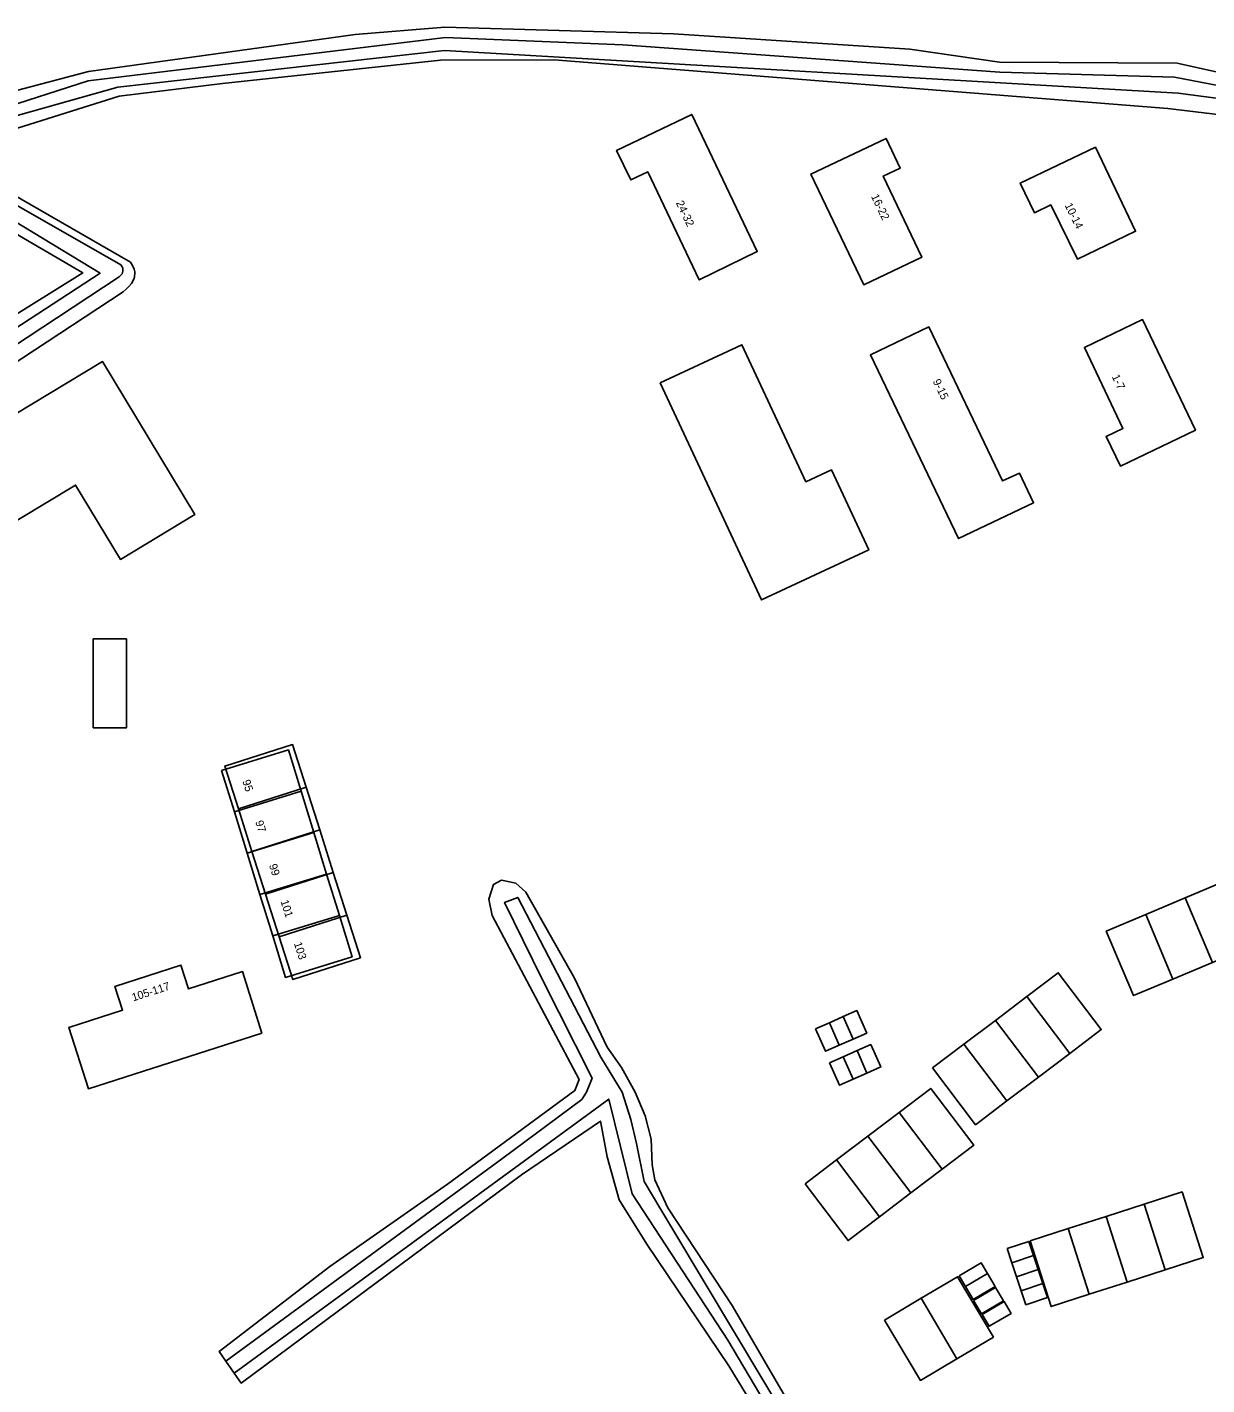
# Model space of a CAD drawing. Extents: x 159451 to 160664, y 388402 to 389723.
# Drawn here: x 159869.7 to 160017.1, y 389378.7 to 389548.3 of the extents above; entities that cross this region are included whole.
import ezdxf

# ---------------------------------------------------------------- set-up
doc = ezdxf.new("R2010")
doc.units = 0
for name, color, linetype in [('IMGEO_Groenvoorziening', 7, 'Continuous'), ('IMGEO_Oever', 7, 'Continuous'), ('IMGEO_Pand', 7, 'Continuous'), ('IMGEO_Pand_nummerreeks', 7, 'Continuous'), ('IMGEO_Pand_vergunning_verleend', 7, 'Continuous'), ('IMGEO_Waterloop', 7, 'Continuous')]:
    doc.layers.add(name, color=color, linetype=linetype)

msp = doc.modelspace()

# ---------------------------------------------------------------- linework, layer by layer
at = {"layer": 'IMGEO_Groenvoorziening'}
for points in [[(159864.26, 389539.27), (159877.37, 389542.72), (159910.67, 389547.35), (159921.89, 389548.25), (159950.46, 389547.42), (159979.98, 389545.51), (159991.18, 389543.87), (160013.37, 389543.74), (160026.85, 389540.77), (160059.3, 389537.37), (160076.74, 389535.9), (160093.1, 389532.4), (160106.88, 389532.52)], [(160094.37, 389528.6), (160093.68, 389522.77), (160090.33, 389523.17), (160090.94, 389528.33), (160076.45, 389531.72), (160041.63, 389534.55), (160012.22, 389538.08), (159935.54, 389544.19), (159921.34, 389544.14), (159894.12, 389541.21), (159881.2, 389539.62), (159858.79, 389532.6), (159882.61, 389518.89), (159882.88, 389518.48), (159883.08, 389518.04), (159883.14, 389517.69), (159883.16, 389517.57), (159883.13, 389517.08), (159883.07, 389516.85), (159882.73, 389516.23), (159882.42, 389515.86), (159882.06, 389515.52), (159881.7, 389515.21), (159821.76, 389475.8)], [(159815.03, 389479.17), (159876.64, 389517.57), (159858.8, 389527.98)], [(159966.8, 389365.6), (159957.37, 389381.03), (159947.14, 389396.23), (159943.66, 389401.77), (159942.19, 389407.16), (159941.35, 389411.59), (159931.47, 389404.89), (159896.45, 389378.88), (159895.58, 389380.11), (159894.54, 389381.6), (159893.69, 389382.82), (159907.5, 389393.46), (159922.23, 389403.72), (159938.12, 389415.41), (159938.68, 389416.82), (159927.82, 389437.27), (159927.38, 389439.33), (159927.97, 389441.16), (159928.96, 389441.71), (159930.75, 389441.34), (159931.99, 389440.21), (159938.08, 389429.46), (159942.16, 389420.84), (159943.96, 389418.29), (159945.66, 389415.23), (159946.9, 389412.25), (159947.66, 389409.36), (159947.78, 389406.13), (159948.12, 389404.27), (159949.76, 389400.78), (159957.78, 389388.59), (159970.06, 389367.46)]]:
    msp.add_lwpolyline(points, dxfattribs=at)
for points in [[(159960.91, 389520.23), (159953.67, 389516.68), (159947.23, 389530.16), (159945.12, 389529.17), (159943.35, 389532.86), (159952.74, 389537.35)], [(159974.22, 389516.08), (159967.63, 389529.9), (159977.01, 389534.35), (159978.78, 389530.65), (159976.67, 389529.64), (159981.49, 389519.54)], [(160000.92, 389519.29), (159997.61, 389526.05), (159995.55, 389525.07), (159993.78, 389528.77), (160003.18, 389533.26), (160008.18, 389522.76)], [(160006.29, 389493.42), (160004.51, 389497.13), (160006.61, 389498.14), (160001.8, 389508.25), (160009.07, 389511.73), (160015.67, 389497.9)], [(159986.07, 389484.37), (159975.08, 389507.33), (159982.35, 389510.81), (159991.56, 389491.57), (159993.67, 389492.55), (159995.44, 389488.85)], [(159906.25, 389447.98), (159907.95, 389442.65), (159909.65, 389437.33), (159911.35, 389432), (159902.88, 389429.3), (159901.19, 389434.63), (159899.49, 389439.96), (159897.79, 389445.29), (159896.1, 389450.61), (159894.39, 389455.96), (159902.86, 389458.64), (159904.55, 389453.31)], [(159899.04, 389422.61), (159877.36, 389415.64), (159874.9, 389423.3), (159881.62, 389425.47), (159880.66, 389428.43), (159888.91, 389431.09), (159889.86, 389428.12), (159896.59, 389430.28)]]:
    msp.add_lwpolyline(points, close=True, dxfattribs=at)
at = {"layer": 'IMGEO_Oever'}
for points in [[(159854.53, 389534.2), (159877.32, 389541.54), (159921.96, 389546.95), (159944.13, 389546.06), (159991.21, 389542.62), (160013.05, 389542.02), (160027.34, 389539.24), (160076.46, 389534.42), (160093.15, 389531.13), (160106.86, 389531.48)], [(160106.88, 389532.52), (160093.1, 389532.4), (160076.74, 389535.9), (160059.3, 389537.37), (160026.85, 389540.77), (160013.37, 389543.74), (159991.18, 389543.87), (159979.98, 389545.51), (159950.46, 389547.42), (159921.89, 389548.25), (159910.67, 389547.35), (159877.37, 389542.72), (159864.26, 389539.27)], [(160101.81, 389529.55), (160093.23, 389529.36), (160092.58, 389524.23), (160091.46, 389524.26), (160091.88, 389529.28), (160076.32, 389532.99), (160052.78, 389534.86), (160013.5, 389540), (159921.84, 389545.35), (159881.02, 389540.75), (159867.27, 389536.87)], [(159821.76, 389475.8), (159881.7, 389515.21), (159882.06, 389515.52), (159882.42, 389515.86), (159882.73, 389516.23), (159883.07, 389516.85), (159883.13, 389517.08), (159883.16, 389517.57), (159883.14, 389517.69), (159883.08, 389518.04), (159882.88, 389518.48), (159882.61, 389518.89), (159858.79, 389532.6), (159881.2, 389539.62), (159894.12, 389541.21), (159921.34, 389544.14), (159935.54, 389544.19), (160012.22, 389538.08), (160041.63, 389534.55), (160076.45, 389531.72), (160090.94, 389528.33), (160090.33, 389523.17), (160093.68, 389522.77), (160094.37, 389528.6)], [(159818.15, 389477.97), (159878.82, 389517.52), (159853.88, 389532.62)], [(159856.18, 389532.97), (159881.4, 389518.55), (159881.57, 389518.31), (159881.65, 389518.15), (159881.67, 389517.77), (159881.56, 389517.46), (159881.41, 389517.26), (159881.21, 389517.06), (159819.88, 389476.66)], [(159858.8, 389527.98), (159876.64, 389517.57), (159815.03, 389479.17)], [(159970.06, 389367.46), (159957.78, 389388.59), (159949.76, 389400.78), (159948.12, 389404.27), (159947.78, 389406.13), (159947.66, 389409.36), (159946.9, 389412.25), (159945.66, 389415.23), (159943.96, 389418.29), (159942.16, 389420.84), (159938.08, 389429.46), (159931.99, 389440.21), (159930.75, 389441.34), (159928.96, 389441.71), (159927.97, 389441.16), (159927.38, 389439.33), (159927.82, 389437.27), (159938.68, 389416.82), (159938.12, 389415.41), (159922.23, 389403.72), (159907.5, 389393.46), (159893.69, 389382.82), (159894.54, 389381.6), (159929.14, 389406.98), (159939.02, 389414.32), (159939.59, 389415.23), (159940.29, 389416.97), (159934.06, 389429.35), (159929.35, 389438.93), (159930.99, 389439.55), (159941.39, 389419.58), (159944.05, 389415.23), (159945.14, 389411.82), (159945.85, 389408.79), (159946.78, 389404.04), (159948.86, 389400.56), (159950.48, 389397.86), (159969.06, 389366.84)], [(159967.9, 389366.27), (159957.24, 389384.26), (159945.31, 389402.53), (159942.37, 389414.35), (159895.58, 389380.11), (159896.45, 389378.88), (159931.47, 389404.89), (159941.35, 389411.59), (159942.19, 389407.16), (159943.66, 389401.77), (159947.14, 389396.23), (159957.37, 389381.03), (159966.8, 389365.6)]]:
    msp.add_lwpolyline(points, dxfattribs=at)
at = {"layer": 'IMGEO_Pand'}
for points in [[(159952.74, 389537.35), (159943.35, 389532.86), (159945.12, 389529.17), (159947.23, 389530.16), (159953.67, 389516.68), (159960.91, 389520.23)], [(159976.67, 389529.64), (159978.78, 389530.65), (159977.01, 389534.35), (159967.63, 389529.9), (159974.22, 389516.08), (159981.49, 389519.54)], [(160003.18, 389533.26), (159993.78, 389528.77), (159995.55, 389525.07), (159997.61, 389526.05), (160000.92, 389519.29), (160008.18, 389522.76)], [(160009.07, 389511.73), (160001.8, 389508.25), (160006.61, 389498.14), (160004.51, 389497.13), (160006.29, 389493.42), (160015.67, 389497.9)], [(159982.35, 389510.81), (159975.08, 389507.33), (159986.07, 389484.37), (159995.44, 389488.85), (159993.67, 389492.55), (159991.56, 389491.57)], [(159902.86, 389458.64), (159894.39, 389455.96), (159896.1, 389450.61), (159904.55, 389453.31)], [(159904.55, 389453.31), (159896.1, 389450.61), (159897.79, 389445.29), (159906.25, 389447.98)], [(159906.25, 389447.98), (159897.79, 389445.29), (159899.49, 389439.96), (159907.95, 389442.65)], [(159907.95, 389442.65), (159899.49, 389439.96), (159901.19, 389434.63), (159909.65, 389437.33)], [(159909.65, 389437.33), (159901.19, 389434.63), (159902.88, 389429.3), (159911.35, 389432)], [(159899.04, 389422.61), (159896.59, 389430.28), (159889.86, 389428.12), (159888.91, 389431.09), (159880.66, 389428.43), (159881.62, 389425.47), (159874.9, 389423.3), (159877.36, 389415.64)]]:
    msp.add_lwpolyline(points, close=True, dxfattribs=at)
at = {"layer": 'IMGEO_Pand_vergunning_verleend'}
for points in [[(159948.81, 389503.83), (159959.01, 389508.58), (159966.98, 389491.47), (159970.19, 389492.97), (159974.85, 389482.95), (159961.44, 389476.7)], [(159859.2, 389494.48), (159879.13, 389506.48), (159890.64, 389487.37), (159881.35, 389481.77), (159875.76, 389491.06), (159865.11, 389484.66)], [(159877.97, 389460.72), (159877.97, 389471.84), (159882.1, 389471.84), (159882.1, 389460.72)], [(159894, 389455.4), (159902.34, 389457.97), (159903.94, 389452.8), (159895.6, 389450.23)], [(159895.6, 389450.23), (159903.94, 389452.8), (159905.53, 389447.64), (159897.19, 389445.07)], [(159897.19, 389445.07), (159905.53, 389447.64), (159907.12, 389442.47), (159898.78, 389439.9)], [(159898.78, 389439.9), (159907.12, 389442.47), (159908.72, 389437.3), (159900.38, 389434.73)], [(160014.38, 389439.49), (160018.94, 389441.42), (160022.34, 389433.35), (160017.78, 389431.43)], [(160009.46, 389437.41), (160014.38, 389439.49), (160017.78, 389431.43), (160012.86, 389429.35)], [(159900.38, 389434.73), (159908.72, 389437.3), (159910.31, 389432.14), (159901.97, 389429.56)], [(160004.53, 389435.34), (160009.46, 389437.41), (160012.86, 389429.35), (160007.93, 389427.28)], [(159994.6, 389427.16), (159998.52, 389430.13), (160003.89, 389423.04), (159999.97, 389420.07)], [(159990.67, 389424.19), (159994.6, 389427.16), (159999.97, 389420.07), (159996.04, 389417.09)], [(159969.93, 389423.9), (159971.65, 389424.66), (159972.89, 389421.85), (159971.17, 389421.09)], [(159971.65, 389424.66), (159973.38, 389425.42), (159974.61, 389422.61), (159972.89, 389421.85)], [(159968.21, 389423.14), (159969.93, 389423.9), (159971.17, 389421.09), (159969.45, 389420.33)], [(159986.75, 389421.21), (159990.67, 389424.19), (159996.04, 389417.09), (159992.12, 389414.12)], [(159973.39, 389420.41), (159975.11, 389421.17), (159976.35, 389418.37), (159974.63, 389417.61)], [(159982.82, 389418.24), (159986.75, 389421.21), (159992.12, 389414.12), (159988.19, 389411.15)], [(159969.94, 389418.89), (159971.67, 389419.65), (159972.91, 389416.85), (159971.18, 389416.08)], [(159971.67, 389419.65), (159973.39, 389420.41), (159974.63, 389417.61), (159972.91, 389416.85)], [(159978.66, 389412.7), (159982.59, 389415.68), (159987.96, 389408.58), (159984.04, 389405.61)], [(159974.74, 389409.73), (159978.66, 389412.7), (159984.04, 389405.61), (159980.11, 389402.64)], [(159970.81, 389406.75), (159974.74, 389409.73), (159980.11, 389402.64), (159976.18, 389399.66)], [(159966.89, 389403.78), (159970.81, 389406.75), (159976.18, 389399.66), (159972.26, 389396.69)], [(160009.25, 389401.23), (160014, 389402.76), (160016.64, 389394.56), (160011.9, 389393.03)], [(160004.51, 389399.7), (160009.25, 389401.23), (160011.9, 389393.03), (160007.15, 389391.5)], [(159999.77, 389398.17), (160004.51, 389399.7), (160007.15, 389391.5), (160002.41, 389389.97)], [(159995.02, 389396.64), (159999.77, 389398.17), (160002.41, 389389.97), (159997.66, 389388.44)], [(159992.14, 389395.68), (159994.86, 389396.58), (159995.44, 389394.83), (159992.72, 389393.92)], [(159992.72, 389393.92), (159995.44, 389394.83), (159996.02, 389393.08), (159993.31, 389392.17)], [(159986.14, 389392.29), (159988.89, 389393.91), (159989.68, 389392.57), (159986.93, 389390.95)], [(159986.93, 389390.95), (159989.68, 389392.57), (159990.64, 389390.96), (159987.89, 389389.34)], [(159993.31, 389392.17), (159996.02, 389393.08), (159996.61, 389391.33), (159993.89, 389390.42)], [(159981.39, 389389.47), (159985.95, 389392.17), (159990.43, 389384.63), (159985.86, 389381.92)], [(159987.95, 389389.2), (159990.7, 389390.82), (159991.67, 389389.17), (159988.92, 389387.55)], [(159993.89, 389390.42), (159996.61, 389391.33), (159997.19, 389389.57), (159994.48, 389388.67)], [(159976.83, 389386.76), (159981.39, 389389.47), (159985.86, 389381.92), (159981.3, 389379.22)], [(159989.02, 389387.44), (159991.77, 389389.06), (159992.64, 389387.59), (159989.89, 389385.97)]]:
    msp.add_lwpolyline(points, close=True, dxfattribs=at)
at = {"layer": 'IMGEO_Waterloop'}
for points in [[(160106.86, 389531.48), (160093.15, 389531.13), (160076.46, 389534.42), (160027.34, 389539.24), (160013.05, 389542.02), (159991.21, 389542.62), (159944.13, 389546.06), (159921.96, 389546.95), (159877.32, 389541.54), (159854.53, 389534.2)], [(159867.27, 389536.87), (159881.02, 389540.75), (159921.84, 389545.35), (160013.5, 389540), (160052.78, 389534.86), (160076.32, 389532.99), (160091.88, 389529.28), (160091.46, 389524.26), (160092.58, 389524.23), (160093.23, 389529.36), (160101.81, 389529.55)], [(159853.88, 389532.62), (159878.82, 389517.52), (159818.15, 389477.97)], [(159819.88, 389476.66), (159881.21, 389517.06), (159881.41, 389517.26), (159881.56, 389517.46), (159881.67, 389517.77), (159881.65, 389518.15), (159881.57, 389518.31), (159881.4, 389518.55), (159856.18, 389532.97)]]:
    msp.add_lwpolyline(points, dxfattribs=at)
msp.add_lwpolyline([(159942.37, 389414.35), (159945.31, 389402.53), (159957.24, 389384.26), (159967.9, 389366.27), (159969.06, 389366.84), (159950.48, 389397.86), (159948.86, 389400.56), (159946.78, 389404.04), (159945.85, 389408.79), (159945.14, 389411.82), (159944.05, 389415.23), (159941.39, 389419.58), (159930.99, 389439.55), (159929.35, 389438.93), (159934.06, 389429.35), (159940.29, 389416.97), (159939.59, 389415.23), (159939.02, 389414.32), (159929.14, 389406.98), (159894.54, 389381.6), (159895.58, 389380.11)], close=True, dxfattribs=at)

# ---------------------------------------------------------------- texts
at = {"layer": 'IMGEO_Pand_nummerreeks'}
for s, rotation, p in [('24-32', 295.5422, (159950.73, 389526.31)), ('16-22', 295.4907, (159975.11, 389527.12)), ('10-14', 296.1095, (159999.3, 389526.01)), ('9-15', 295.5652, (159982.83, 389504.02)), ('1-7', 295.4277, (160005.19, 389504.61)), ('95', 287.6698, (159896.57, 389454.08)), ('97', 287.6698, (159898.19, 389448.99)), ('99', 287.6698, (159899.91, 389443.57)), ('101', 287.6698, (159901.35, 389439.07)), ('103', 287.6698, (159903.02, 389433.81)), ('105-117', 17.8763, (159882.96, 389426.55))]:
    msp.add_text(s, height=1, rotation=rotation, dxfattribs=at).set_placement(p)

doc.saveas('drawing.dxf')
